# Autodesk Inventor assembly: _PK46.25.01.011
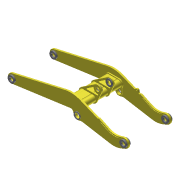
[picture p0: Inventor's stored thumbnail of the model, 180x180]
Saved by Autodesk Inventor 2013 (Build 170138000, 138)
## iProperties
Created: 2005-04
Part Number: _PK46.25.01.011
Document SubType Name: Assembly
Designer: salex
Manufacturer: Standard
Standards Organization: Custom
Author: salex
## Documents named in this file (8)
- C:\Product Design Suite 2013\Chassis, Front_Layout\Workspace\Assy, Chassis, Front\PK46.25.01.011.iam
- C:\Product Design Suite 2013\Chassis, Front_Layout\Workspace\Assy, Chassis, Front\PK46.25.01.001.ipt
- C:\Product Design Suite 2013\Chassis, Front_Layout\Workspace\Assy, Chassis, Front\PK46.25.01.002.ipt
- C:\Product Design Suite 2013\Chassis, Front_Layout\Workspace\Assy, Chassis, Front\PK46.25.01.003.ipt
- C:\Product Design Suite 2013\Chassis, Front_Layout\Workspace\Assy, Chassis, Front\PK46.25.01.004.ipt
- C:\Product Design Suite 2013\Chassis, Front_Layout\Workspace\Assy, Chassis, Front\PK46.25.01.008.ipt
- C:\Product Design Suite 2013\Chassis, Front_Layout\Workspace\Assy, Chassis, Front\PK46.25.01.012.ipt
- C:\Product Design Suite 2013\Chassis, Front_Layout\Workspace\Assy, Chassis, Front\PK46.25.01.021.iam
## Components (19 placed, 7 different names)
1. PK46.25.01.001:1 — Insert:3, Insert:4, Insert:7, Insert:8, Mate:1, Mate:2, Mate:3, Insert:10, Insert:11, Angle:1
2. PK46.25.01.002:1 — Insert:1, Insert:2, Insert:5, Insert:6, Mate:1, Mate:2, Mate:3, Insert:9, Insert:12, Angle:2, Mate:9, Mate:10
3. PK46.25.01.003:1 — Insert:3, Insert:14
4. PK46.25.01.003:2 — Insert:4, Insert:16
5. PK46.25.01.003:3 — Insert:1, Insert:13
6. PK46.25.01.003:4 — Insert:2, Insert:15
7. PK46.25.01.003:5 — Insert:5
8. PK46.25.01.003:6 — Insert:6
9. PK46.25.01.003:7 — Insert:7
10. PK46.25.01.003:8 — Insert:8
11. PK46.25.01.004:1 — Insert:10
12. PK46.25.01.004:2 — Insert:9
13. PK46.25.01.008:1 — Insert:11, Mate:6, Mate:7, Mate:8
14. PK46.25.01.008:2 — Insert:12, Mate:4, Mate:5
15. PK46.25.01.012:1 — Insert:15
16. PK46.25.01.012:2 — Insert:16, Angle:1
17. PK46.25.01.012:3 — Insert:13, Angle:2
18. PK46.25.01.012:4 — Insert:14
19. PK46.25.01.021:1 [sub-assembly] — Mate:4, Mate:5, Mate:6, Mate:7, Mate:8, Mate:14, Flush:1, Flush:5, Angle:4, Mate:20, Mate:21
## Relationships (34: Insert 16, Mate 13, Angle 3, Flush 2)
- Insert:1: PK46.25.01.002:1 ↔ PK46.25.01.003:3
- Insert:2: PK46.25.01.002:1 ↔ PK46.25.01.003:4
- Insert:3: PK46.25.01.001:1 ↔ PK46.25.01.003:1
- Insert:4: PK46.25.01.001:1 ↔ PK46.25.01.003:2
- Insert:5: PK46.25.01.002:1 ↔ PK46.25.01.003:5
- Insert:6: PK46.25.01.002:1 ↔ PK46.25.01.003:6
- Insert:7: PK46.25.01.001:1 ↔ PK46.25.01.003:7
- Insert:8: PK46.25.01.001:1 ↔ PK46.25.01.003:8
- Mate:1: PK46.25.01.001:1 ↔ PK46.25.01.002:1
- Mate:2: PK46.25.01.001:1 ↔ PK46.25.01.002:1
- Mate:3: PK46.25.01.001:1 ↔ PK46.25.01.002:1
- Insert:9: PK46.25.01.002:1 ↔ PK46.25.01.004:2
- Insert:10: PK46.25.01.001:1 ↔ PK46.25.01.004:1
- Insert:11: PK46.25.01.001:1 ↔ PK46.25.01.008:1
- Insert:12: PK46.25.01.002:1 ↔ PK46.25.01.008:2
- Mate:4: PK46.25.01.008:2 ↔ PK46.25.01.021:1
- Mate:5: PK46.25.01.008:2 ↔ PK46.25.01.021:1
- Mate:6: PK46.25.01.008:1 ↔ PK46.25.01.021:1
- Mate:7: PK46.25.01.008:1 ↔ PK46.25.01.021:1
- Mate:8: PK46.25.01.008:1 ↔ PK46.25.01.021:1
- Insert:13: PK46.25.01.003:3 ↔ PK46.25.01.012:3
- Insert:14: PK46.25.01.003:1 ↔ PK46.25.01.012:4
- Insert:15: PK46.25.01.003:4 ↔ PK46.25.01.012:1
- Insert:16: PK46.25.01.003:2 ↔ PK46.25.01.012:2
- Angle:1: PK46.25.01.001:1 ↔ PK46.25.01.012:2
- Angle:2: PK46.25.01.002:1 ↔ PK46.25.01.012:3
- Mate:9: PK46.25.01.002:1
- Mate:10: PK46.25.01.002:1
- Mate:14: PK46.25.01.021:1
- Flush:1: PK46.25.01.021:1
- Flush:5: PK46.25.01.021:1
- Angle:4: PK46.25.01.021:1
- Mate:20: PK46.25.01.021:1
- Mate:21: PK46.25.01.021:1
